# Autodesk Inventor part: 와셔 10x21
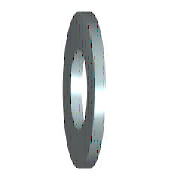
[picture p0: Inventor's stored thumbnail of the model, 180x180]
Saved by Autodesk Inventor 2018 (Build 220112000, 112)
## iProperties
Created: 2012-02
Part Number: 와셔 10x21
Material: 강철, 연강
Description: 평면 와셔
Document SubType Name: Modeling
Standard: KS B 1326
Designer: mduedu
Standards Organization: KS
Language: ko-KR
Size Designation: 10x21
Categories: <MemberInstance><Categories><Category DisplayName="조임쇠" InternalName="e4da775c-781d-43d5-af7c-5136215cf5a6" Mnemonic="FSTN"><Category DisplayName="와셔" InternalN
Density: 1 g/cm^3
Appearance: 파란색 - 벽 페인트 - 광택
IsCustomPart: 1
Author: mduedu
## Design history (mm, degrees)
sketch "스케치"
  geometry: C1 r 10.5 at (0, 0); C2 r 5.25 at (0, 0); 1 further point
  constraints: 2 centre point, 2 coincident
  dimensions: "d0" = 10.5 diameter of C2 (= SD1); "d1" = 21 diameter of C1 (= SD2)
extrude "본체" new body sketch "스케치" distance "d2" = 2 (= SD); taper "d3" = 0 deg
workaxis "Work Axis1"
workplane "Work Plane1"
body "Solid1"
other parameters: "SD1" = 10.5 [user parameter; used in 1 equation term], "SD2" = 21 [user parameter; used in 1 equation term], "SD" = 2 [user parameter; used in 1 equation term], "d4" = 0, "d5" = 0, "d6" = 0, "d7" = 0
